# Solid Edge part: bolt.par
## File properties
Author: Sarvanan
Template: sync ansi part.par
Last saved by: CADCIM
Revision: 13
Application: Solid Edge
Accuracy: 0.990
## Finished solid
Body 1: solid body, 11 faces, 21 edges, 12 vertices.
  Faces by surface: plane 9, cone 1, cylinder 1
  Edges by curve: line 12, intersection 6, circle 3
Bounding box of the edges (mm): 7.620 x 8.799 x 81.280, from (-0.0184, -5.4708, -78.74) to (7.6016, 3.328, 2.54).
Cylindrical faces by radius (mm): R3.3834 x1
Conical faces (half-angle, radius in mm at the cone's reference point): 45 deg R4.3994 x1
Planar faces by outward normal: +x 1, +z 1, -x 1, -z 2, oblique 4
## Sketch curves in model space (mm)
circle centre (3.7916, -1.0714, 2.54) radius 3.302
line (3.7916, -1.0714, 2.54) -> (7.175, -1.0714, 2.54)
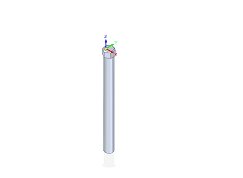
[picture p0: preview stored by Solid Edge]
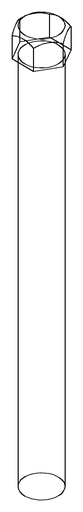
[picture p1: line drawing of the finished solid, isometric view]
